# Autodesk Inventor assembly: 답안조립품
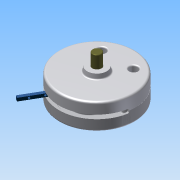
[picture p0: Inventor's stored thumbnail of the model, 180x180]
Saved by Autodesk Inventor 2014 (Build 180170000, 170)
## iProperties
Created: 2015-06
Part Number: 답안조립품
Document SubType Name: Assembly
Designer: Administrator
Author: Administrator
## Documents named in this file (10)
- C:\Documents and Settings\Administrator\바탕 화면\450631V1018\답안조립품.iam
- C:\Documents and Settings\Administrator\바탕 화면\450631V1018\1-본체.ipt
- C:\Documents and Settings\Administrator\바탕 화면\450631V1018\덮개.ipt
- C:\Documents and Settings\Administrator\바탕 화면\450631V1018\베어링62_22.ipt
- C:\Documents and Settings\Administrator\바탕 화면\450631V1018\축.ipt
- C:\Documents and Settings\Administrator\바탕 화면\450631V1018\멈춤링.ipt
- C:\Documents and Settings\Administrator\바탕 화면\450631V1018\슬라이더.ipt
- C:\Documents and Settings\Administrator\바탕 화면\450631V1018\평행핀.ipt
- C:\Documents and Settings\Administrator\바탕 화면\450631V1018\슬라이더2.ipt
- C:\Documents and Settings\Administrator\바탕 화면\450631V1018\M10x35.ipt
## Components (8 placed, 5 different names)
1. 1-본체:1 — 각도:1
2. KS B 2023 62/22 - 22 x 50 x 14:1
3. KS B 2023 62/22 - 22 x 50 x 14:2
4. KS B 1336 22 x 1.2:1
5. KS B 1336 22 x 1.2:2
6. KS B 1320 B B 5 x  20:1 — 플러쉬:1
7. KS B 1003 - 미터 M 10 x 35:1
8. KS B 1003 - 미터 M 10 x 35:2
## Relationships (2: Flush 1, Angle 1)
- 플러쉬:1 [Flush]: KS B 1320 B B 5 x  20:1
- 각도:1 [Angle]: 1-본체:1
